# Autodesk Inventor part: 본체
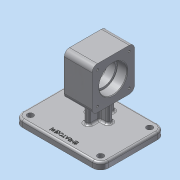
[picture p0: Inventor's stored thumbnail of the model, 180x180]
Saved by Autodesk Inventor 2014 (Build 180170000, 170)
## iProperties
Created: 2020-11
Part Number: 본체
Material: 알루미늄 6061
Document SubType Name: Modeling
Designer: kh
Density: 2.71 g/cm^3
Appearance: 알루미늄 - 평지
Mass: 691.869 g
Surface Area: 548.551 cm^2
Volume: 255.302 cm^3
Author: kh
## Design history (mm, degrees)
sketch "스케치1"
  geometry: L1 (63.86, -49)-(-66.14, -49); L2 (-66.14, -49)-(-66.14, 49); L3 (-66.14, 49)-(63.86, 49); L4 (63.86, 49)-(63.86, -49); L5 (63.86, -49)-(-66.14, 49); L6 (-66.14, -49)-(63.86, 49); 2 further points
  constraints: 12 end point, 2 midpoint, 2 parallel, 1 horizontal, 1 perpendicular
  dimensions: "d0" = 130 distance of L2.end L3.end; "d1" = 98 distance of L1.end L2.end
extrude "돌출1" new body sketch "스케치1" distance "d2" = 10; taper "d3" = 0 deg
sketch "스케치3"
  geometry: 1 further point
sketch "스케치4"
  geometry: L1 (-19, 102)-(45, 102); L2 (45, 102)-(45, 38); L3 (45, 38)-(-19, 38); L4 (-19, 38)-(-19, 102); L5 (-19, 102)-(45, 38); L6 (45, 102)-(-19, 38); L7 (49, 0)-(-49, 0) reference; L8 (49, 0)-(49, 10) reference; L9 (-49, 10)-(49, 10) reference; L10 (-49, 0)-(-49, 10) reference; L11 (49, 0)-(-49, 0) reference; 4 further points
  constraints: 12 end point, 2 midpoint, 2 parallel, 1 coincident, 1 horizontal, 1 perpendicular
  dimensions: "d4" = 64 distance of L1.start L1.end; "d5" = 64 distance of L3.end L1.start; "d43" = 62 distance from line of L10 point (13, 70); "d122" = 70 distance from line of L7 point (13, 70)
extrude "돌출2" join sketch "스케치4" stored distance "d7" = 42; taper "d8" = 0 deg
sketch "스케치9"
  geometry: L1 (-102, 45)-(-102, -19) reference; L2 (-102, -19)-(-38, -19) reference; L3 (-38, -19)-(-38, 45) reference; L4 (-38, 45)-(-102, 45) reference; L5 (0, 49)-(0, -49) reference; C1 r 18 at (-70, 13); 1 further point
  constraints: 1 centre point
  dimensions: "d46" = 36 diameter of C1; "d123" = 70 distance from line of C1.centre L5
extrude "돌출4" cut sketch "스케치9" distance "d47" = 42; taper "d48" = 0 deg
hole "구멍4" diameter "d51" = 42; stored, may be unused: countersink angle "d55" = 90 deg, drill point angle "d57" = 0 deg; dims "d49" = 10, "d50" = 10, "d52" = 8, "d53" = 42, "d54" = 15, "d56" = 15
sketch "스케치11"
  geometry: L1 (33, 38)-(33, 10); L2 (-19, 102)-(45, 102) reference; L3 (45, 102)-(45, 38) reference; L4 (45, 38)-(-19, 38) reference; L5 (-19, 38)-(-19, 102) reference; L6 (-49, 0)-(49, 0) reference; L7 (-49, 0)-(-49, 10) reference; L8 (49, 10)-(-49, 10) reference; L9 (49, 0)-(49, 10) reference; L10 (13, 70)-(13, 107.568); L11 (-7, 38)-(-7, 10); L12 (-7, 38)-(33, 38); L13 (-7, 10)-(33, 10); C1 r 21 at (13, 70) reference; 1 further point
  constraints: 10 end point, 2 collinear, 2 point on line, 2 symmetric about line, 1 parallel, 1 vertical
  dimensions: "d60" = 20 distance between parallel lines of L1 L10
extrude "돌출5" join sketch "스케치11" stored distance "d61" = 8; taper "d62" = 0 deg
node "작업 평면2"
sketch "스케치18"
  geometry: L1 (38, 64)-(38, 92); L2 (42, 64)-(0, 64) reference; L3 (42, 0)-(42, 64) reference; L4 (0, 0)-(42, 0) reference; L5 (0, 64)-(0, 0) reference; L6 (0, 0)-(42, 0) reference; L7 (42, 0)-(0, 0) reference; L8 (42, 64)-(42, 0) reference; L9 (42, 64)-(0, 64) reference; L10 (0, 0)-(0, 64) reference; L11 (-45.14, 102)-(84.86, 102) reference; L12 (-45.14, 102)-(-45.14, 92) reference; L13 (84.86, 92)-(-45.14, 92) reference; L14 (84.86, 102)-(84.86, 92) reference; 1 further point
  constraints: 2 end point, 2 point on line, 1 vertical
  dimensions: "d74" = 17 horizontal distance of point (21, 102) L1.end
feature "리브2" sketch "스케치18" dims "d75" = 1, "d76" = 8, "d77" = 0, "d78" = 0, "d79" = 1, "d80" = 1
sketch "스케치19"
  geometry: L1 (-102, 45)-(-102, -19) reference; L2 (-102, -19)-(-38, -19) reference; L3 (-38, -19)-(-38, 45) reference; L4 (-38, 45)-(-102, 45) reference; C1 r 21 at (-70, 13) reference; 2 further points
  dimensions: "d81" = 24 horizontal distance of C1.centre point (-94, -11); "d82" = 24 horizontal distance of C1.centre point (-94, -11)
hole "구멍5" sketch "스케치19" at (-94, -11) diameter "d83" = 3.242; stored, may be unused: countersink angle "d87" = 90 deg, drill point angle "d89" = 118 deg; dims "d84" = 8, "d85" = 42, "d86" = 15, "d88" = 10
fillet "모깎기1" dims "d96" = 12
hole "구멍6" diameter "d99" = 9; stored, may be unused: countersink angle "d103" = 90 deg, drill point angle "d105" = 0 deg; dims "d97" = 10, "d98" = 10, "d100" = 8, "d101" = 42, "d102" = 15, "d104" = 10
fillet "모깎기2" dims "d110" = 0.3
fillet "모깎기3" dims "d111" = 8
fillet "모깎기4" dims "d112" = 3
fillet "모깎기5" dims "d113" = 3
fillet "모깎기6" dims "d114" = 3
sketch "스케치20" dims "d49" = 10, "d50" = 10
  geometry: L1 (-66.14, 37)-(-66.14, -37) reference; L2 (-54.14, -49)-(51.86, -49) reference; 2 further points
  constraints: 1 other
  dimensions: "d115" = 65 distance from line of L1 point (-1.14, -39); "d116" = 10 distance from line of L2 point (-1.14, -39)
feature "엠보싱1" sketch "스케치20" dims "d0" = 130, "d1" = 98, "d117" = 0.5, "d118" = 0
chamfer "모따기1" distance "d119" = 1; stored, may be unused: second distance "d120" = 2, angle "d121" = 45 deg
node "솔리드1"
mirror "대칭2"
mirror "대칭3"
pattern_linear "직사각형 패턴2" dims "d92" = 48, "d95" = 48
mirror "대칭4"
pattern_linear "직사각형 패턴3"
node "투영된 루프1"
node "투영된 루프6"
node "투영된 루프7"
node "투영된 루프8"
node "투영된 루프14"
node "투영된 루프15"
node "투영된 루프16"
node "투영된 루프17"
other parameters: "d73" = -32
